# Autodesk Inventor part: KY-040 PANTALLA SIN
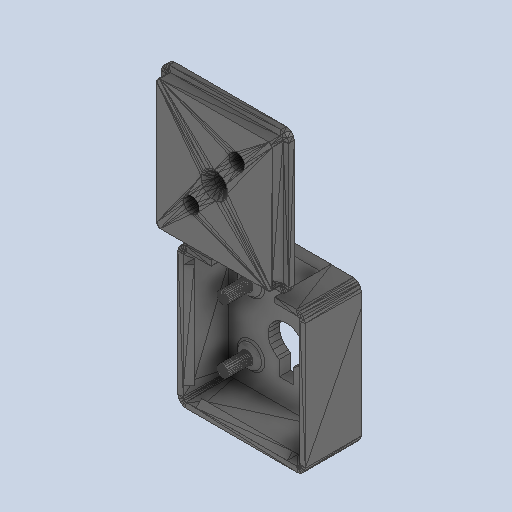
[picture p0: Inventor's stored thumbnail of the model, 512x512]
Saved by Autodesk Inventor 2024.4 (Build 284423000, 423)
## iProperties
Created: 2025-06
Part Number: KY-040 PANTALLA SIN
Material: Generic
Document SubType Name: Modeling
Designer: AdminForWorker
Density: 1 g/cm^3
Appearance: Default
Title: KY-040 PANTALLA SIN v5
Author: AdminForWorker
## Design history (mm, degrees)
feature "CUBIERTA_KY040"
feature "BASE_KY040"
body "Solid1"
body "Solid2"
